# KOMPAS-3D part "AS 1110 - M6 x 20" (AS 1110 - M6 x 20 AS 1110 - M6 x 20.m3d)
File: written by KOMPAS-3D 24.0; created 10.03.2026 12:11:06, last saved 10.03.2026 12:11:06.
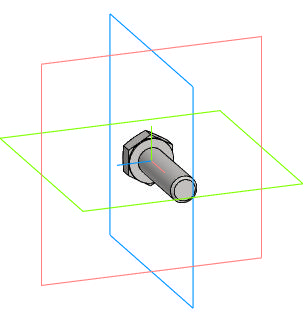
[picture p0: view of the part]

Document properties: Автор: R2D2; Полное имя файла: E:\Работа\Зайцев\BV3232P(4pc)-FP-3WL-F-ISO-H Кран шаровой DN.ru Ду15-100 Ру16\DN25\исходные материалы\AS 1110 - M6 x 20 AS 1110 - M6 x 20.m3d

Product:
- Body: Solid1  | qty 1
- Part/product: AS 1110 - M6 x 20
    Комментарий: Болты и винты   шестигранные точные   метрические ISO
    additional columns: Сталь, мягкая

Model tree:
1. Solid1  (labels: Solid1)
